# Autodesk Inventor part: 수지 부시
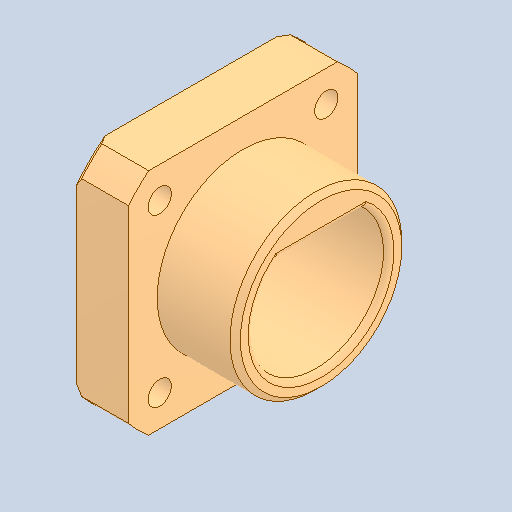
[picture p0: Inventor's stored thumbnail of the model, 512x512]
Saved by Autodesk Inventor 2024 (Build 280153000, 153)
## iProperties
Created: 2024-10
Part Number: 수지 부시
Material: ABS 플라스틱
Document SubType Name: Modeling
Designer: user
Density: 1.06 g/cm^3
Appearance: 기본값
Author: jhkim
Sending System: Autodesk Inventor 2025
Preprocessor: ST-DEVELOPER v20
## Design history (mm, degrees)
feature "솔리드1"
node "솔리드2"
